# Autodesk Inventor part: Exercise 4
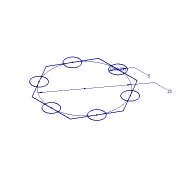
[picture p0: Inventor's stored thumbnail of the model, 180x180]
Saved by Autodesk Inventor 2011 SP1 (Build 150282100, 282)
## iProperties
Created: 2010-11
Part Number: Exercise 4
Document SubType Name: Modeling
Designer: SERGIO
Density: 1 g/cm^3
Author: SERGIO
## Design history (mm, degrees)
sketch "Sketch1" dims "d5" = 25
  geometry: L1 (7.217, 12.5)-(14.434, 0); L2 (14.434, 0)-(7.217, -12.5); L3 (7.217, -12.5)-(-7.217, -12.5); L4 (-7.217, -12.5)-(-14.434, 0); L5 (-14.434, 0)-(-7.217, 12.5); L6 (-7.217, 12.5)-(7.217, 12.5); C1 r 2.5 at (0, 12.5); C2 r 2.5 at (-10.825, 6.25); C3 r 2.5 at (-10.825, -6.25); C4 r 2.5 at (0, -12.5); C5 r 2.5 at (10.825, -6.25); C6 r 2.5 at (10.825, 6.25); 3 further points
  constraints: 12 end point, 6 centre point, 2 coincident, 2 vertical alignment, 1 midpoint, 28 other
  dimensions: "d0" = 5 diameter of C1; "d3" = 360 deg dimension on point (0, 0) C1.centre (derived)
